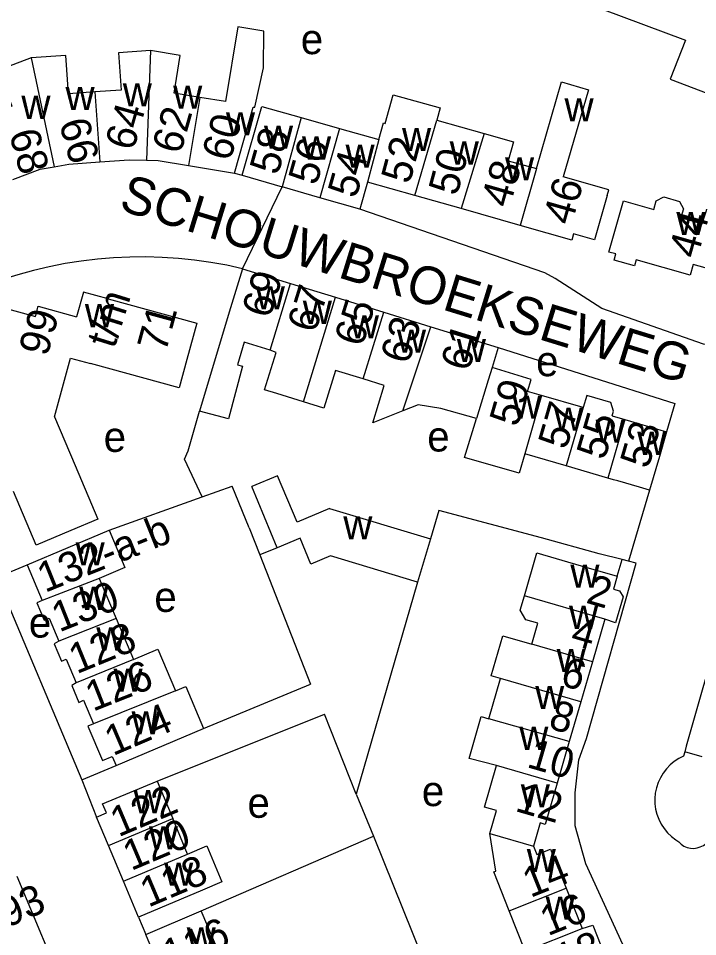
# Model space of a CAD drawing. Extents: x 159261 to 160849, y 382514 to 384534.
# Drawn here: x 159917.5 to 160007.7, y 383430.4 to 383552.3 of the extents above; entities that cross this region are included whole.
import ezdxf

# ---------------------------------------------------------------- set-up
doc = ezdxf.new("R2010")
doc.units = 0
for name, color, linetype in [('BLT_Basislijn', 7, 'Continuous'), ('BLT_Bebouwing', 7, 'Continuous'), ('BLT_Centroide', 7, 'Continuous'), ('BLT_Huisnummer', 7, 'Continuous'), ('BLT_Huisnummer_ tussenligend', 7, 'Continuous'), ('BLT_Huisnummer_reeks', 7, 'Continuous'), ('BLT_Onderverdeling_panden', 7, 'Continuous'), ('BLT_Straatnaam', 7, 'Continuous'), ('BLT_Vlakafsluiter', 7, 'Continuous')]:
    doc.layers.add(name, color=color, linetype=linetype)

msp = doc.modelspace()

# ---------------------------------------------------------------- linework, layer by layer
at = {"layer": 'BLT_Basislijn'}
for p, q in [((159941.95, 383488.76), (159945.92, 383490.19)), ((159948.18, 383484.66), (159945.92, 383490.19)), ((159929.56, 383484.35), (159941.95, 383488.76)), ((160001.36, 383489.65), (159998.56, 383480.21)), ((159951.91, 383482.01), (159949.6, 383481.04)), ((159997.06, 383478.21), (159997.72, 383480.42)), ((159914.62, 383478.06), (159918.68, 383479.74)), ((159914.62, 383478.06), (159925.95, 383451.2)), ((159970.55, 383477.43), (159962.4, 383449.28)), ((159942.13, 383457.98), (159956.32, 383463.89)), ((159935.97, 383451.01), (159958.18, 383459.92)), ((159962.4, 383449.28), (159958.18, 383459.92)), ((160008.35, 383454.22), (160006.03, 383454.89)), ((159925.95, 383451.2), (159930.51, 383453.07)), ((159925.95, 383451.2), (159927.91, 383446.24)), ((159962.4, 383449.28), (159964.68, 383443.7)), ((159941.82, 383433.77), (159964.68, 383443.7)), ((159964.68, 383443.7), (159978.73, 383408.97)), ((159926.45, 383416.69), (159917.36, 383438.35)), ((159933.48, 383432.95), (159934.45, 383430.65))]:
    msp.add_line(p, q, dxfattribs=at)
for points in [[(159935.34, 383566.83), (159950.74, 383571.9), (159950.72, 383570.15), (160006.11, 383549.4), (160004.08, 383544.22), (160019.68, 383538.31)], [(159946.23, 383531.75), (159947.26, 383531.47)], [(160016.26, 383531.1), (160010.01, 383508.78), (160008.53, 383509.02), (159995, 383513.79), (159988.8, 383517.76), (159987.45, 383518.5), (159962.86, 383526.95)], [(159947.3, 383519.06), (159945.19, 383519.52), (159943.07, 383519.9), (159940.93, 383520.2), (159938.79, 383520.42), (159936.63, 383520.56), (159934.47, 383520.62), (159932.32, 383520.61), (159930.16, 383520.51), (159928.01, 383520.33), (159925.87, 383520.07), (159923.73, 383519.74), (159921.62, 383519.32), (159919.52, 383518.83), (159917.43, 383518.26), (159915.38, 383517.61), (159913.34, 383516.89), (159911.34, 383516.09), (159909.36, 383515.22), (159907.42, 383514.27), (159905.52, 383513.26), (159903.65, 383512.17), (159901.83, 383511.02), (159900.97, 383510.44)], [(159981.27, 383508.6), (160004.73, 383501.16), (160003.61, 383497.41)], [(159941.95, 383488.76), (159939.57, 383493.78), (159940.06, 383494.87), (159941.59, 383500.13)], [(159973.38, 383486.97), (159972.28, 383483.18)], [(159997.72, 383480.42), (159994.68, 383481.19), (159987.01, 383483.34), (159973.38, 383486.97)], [(159948.18, 383484.66), (159949.6, 383481.04)], [(159949.6, 383481.04), (159956.32, 383463.89)], [(160008.79, 383416.3), (160007.65, 383418.48), (160006.78, 383418.91), (160000.03, 383424.5), (159992.9, 383440.01), (159991.46, 383445.07), (159991.46, 383449.46), (159991.95, 383453.84), (159992.99, 383456.67), (159999.56, 383479.96), (159998.56, 383480.21)], [(159998.56, 383480.21), (159997.72, 383480.42)], [(160011.91, 383475.28), (160008.45, 383463.41), (160006.23, 383455.63), (160006.03, 383454.89)], [(160006.03, 383454.89), (160005.87, 383454.33)], [(160005.87, 383454.33), (160005.24, 383454.01), (160004.64, 383453.62), (160004.09, 383453.16), (160003.59, 383452.64), (160003.16, 383452.08), (160002.79, 383451.46), (160002.49, 383450.81), (160002.27, 383450.13), (160002.12, 383449.43), (160002.06, 383448.72), (160002.07, 383448.01), (160002.16, 383447.3), (160002.34, 383446.61), (160002.58, 383445.94), (160002.9, 383445.3), (160003.3, 383444.7), (160003.75, 383444.15), (160004.26, 383443.65), (160004.83, 383443.21), (160005.24, 383442.96)], [(160005.24, 383442.96), (160005.56, 383442.64), (160005.93, 383442.39), (160006.34, 383442.21), (160006.78, 383442.11), (160007.23, 383442.08), (160007.67, 383442.13), (160008.1, 383442.26), (160008.5, 383442.47), (160008.86, 383442.74), (160009.16, 383443.07), (160009.4, 383443.45), (160009.6, 383443.95)]]:
    msp.add_lwpolyline(points, dxfattribs=at)
at = {"layer": 'BLT_Bebouwing'}
for p, q in [((159955.1, 383539.13), (159960.16, 383537.69)), ((159940.11, 383532.77), (159946.23, 383531.75)), ((159963.89, 383530.56), (159962.86, 383526.95)), ((159970.2, 383528.77), (159963.89, 383530.56)), ((159957.55, 383528.49), (159952.54, 383529.94)), ((159962.86, 383526.95), (159957.55, 383528.49)), ((159976.32, 383527.04), (159970.2, 383528.77)), ((159995.71, 383528.78), (159994.05, 383522.91)), ((159984.17, 383524.81), (159976.32, 383527.04)), ((159987.74, 383523.8), (159984.17, 383524.81)), ((159991.04, 383522.86), (159987.74, 383523.8)), ((159991.27, 383523.69), (159991.04, 383522.86)), ((159994.05, 383522.91), (159991.27, 383523.69)), ((159947.3, 383519.06), (159953.68, 383517.09)), ((159953.68, 383517.09), (159959.64, 383515.26)), ((159959.64, 383515.26), (159966.04, 383513.29)), ((159966.04, 383513.29), (159972.29, 383511.36)), ((159972.29, 383511.36), (159981.27, 383508.6)), ((159981.27, 383508.6), (159980.45, 383505.94)), ((159922.33, 383499.38), (159924.46, 383507.19)), ((159924.46, 383507.19), (159927.12, 383506.47)), ((159992.53, 383500.62), (159987.02, 383502.22)), ((159922.33, 383499.38), (159925.06, 383492.91)), ((159996.38, 383499.51), (159998.07, 383499.02)), ((159998.07, 383499.02), (160000, 383498.46)), ((160000, 383498.46), (160003.61, 383497.41)), ((160003.61, 383497.41), (160002.66, 383494.11)), ((159990.29, 383492.86), (159984.77, 383494.46)), ((160002.66, 383494.11), (160001.36, 383489.65)), ((159995.82, 383491.25), (159990.29, 383492.86)), ((159951.91, 383482.01), (159948.54, 383490.12)), ((160001.36, 383489.65), (160000, 383490.04)), ((159918.68, 383479.74), (159929.56, 383484.35)), ((159918.68, 383479.74), (159920.67, 383474.98)), ((159928.27, 383477.92), (159930.52, 383472.61)), ((159930.52, 383472.61), (159932.82, 383467.17)), ((159995.41, 383472.5), (159993.77, 383466.86)), ((159993.77, 383466.86), (159992.23, 383461.55)), ((159992.23, 383461.55), (159990.69, 383456.27)), ((159930.51, 383453.07), (159942.13, 383457.98)), ((159990.69, 383456.27), (159989.09, 383450.75)), ((159935.97, 383451.01), (159938.02, 383446.06)), ((159929.49, 383442.46), (159927.91, 383446.24)), ((159939.98, 383441.31), (159938.02, 383446.06)), ((159931.48, 383437.72), (159929.49, 383442.46)), ((159933.48, 383432.95), (159931.48, 383437.72)), ((159990.28, 383436.77), (159992.39, 383431.42)), ((159944.95, 383426.37), (159941.82, 383433.77)), ((159984.83, 383428.44), (159982.72, 383433.78)), ((159937.58, 383423.24), (159934.45, 383430.65))]:
    msp.add_line(p, q, dxfattribs=at)
for points in [[(159948.95, 383540.5), (159950.1, 383545.73), (159950.13, 383550.61), (159946.66, 383551.18), (159945.01, 383541.25), (159941.61, 383541.81)], [(159927.68, 383542.54), (159924.18, 383542.3), (159923.83, 383547.37), (159919.23, 383547.05)], [(159935.09, 383548.05), (159930.83, 383547.75), (159931.18, 383542.78), (159927.68, 383542.54)], [(159941.61, 383541.81), (159938.21, 383542.38), (159939.02, 383547.36), (159935.09, 383548.05)], [(159919.23, 383547.05), (159914.87, 383545.43), (159916.65, 383540.64), (159913.57, 383539.5)], [(159986.35, 383532.37), (159989.67, 383543.87), (159993.25, 383542.82), (159989.88, 383531.27)], [(159965.4, 383536.21), (159966.02, 383538.42), (159966.23, 383538.36), (159967.31, 383542.17), (159973.55, 383540.41), (159973.1, 383538.8)], [(159946.23, 383531.75), (159948.71, 383540.53), (159948.95, 383540.5)], [(159947.26, 383531.47), (159949.85, 383540.62), (159955.1, 383539.13)], [(159973.1, 383538.8), (159979.41, 383537.01)], [(159960.16, 383537.69), (159965.4, 383536.21)], [(159979.41, 383537.01), (159983.29, 383535.91), (159982.57, 383533.4), (159986.35, 383532.37)], [(159922.28, 383532.6), (159924.21, 383532.96), (159928.32, 383533.25)], [(159928.32, 383533.25), (159932.22, 383533.52), (159934.53, 383533.47)], [(159934.53, 383533.47), (159936.07, 383533.44), (159940.11, 383532.77)], [(159916.77, 383530.9), (159920.41, 383532.26), (159922.28, 383532.6)], [(159947.26, 383531.47), (159952.54, 383529.94)], [(159995.71, 383528.78), (159995.96, 383529.55), (159989.88, 383531.27)], [(159947.3, 383519.06), (159945.52, 383513.28), (159941.59, 383500.13)], [(159929.46, 383515.05), (159926.15, 383515.94), (159925.26, 383512.68)], [(159929.46, 383515.05), (159941.21, 383511.84), (159939.89, 383507.02), (159938.87, 383503.26), (159927.12, 383506.47)], [(159912.03, 383502.09), (159911.52, 383502.23), (159914.76, 383514.09), (159919.78, 383512.72), (159920.15, 383514.08), (159925.26, 383512.68)], [(159950.95, 383508.23), (159947.53, 383509.29), (159946.62, 383506.31), (159947.3, 383506.13), (159945.41, 383499.12), (159941.59, 383500.13)], [(159955.38, 383501.4), (159951.87, 383502.48), (159950.23, 383502.98), (159951.76, 383507.93), (159950.95, 383508.23)], [(159987.02, 383502.22), (159985.14, 383502.77), (159985.62, 383504.35), (159980.45, 383505.94)], [(159963.3, 383504.42), (159959.64, 383505.55), (159958.11, 383500.56), (159955.38, 383501.4)], [(159968.58, 383500.18), (159964.59, 383498.59), (159966.12, 383503.55), (159963.3, 383504.42)], [(159996.38, 383499.51), (159996.56, 383500.14), (159996.23, 383501.29), (159993.01, 383502.24), (159992.53, 383500.62)], [(159978.36, 383499.15), (159973.64, 383500.5), (159970.63, 383501), (159968.58, 383500.18)], [(159984.77, 383494.46), (159984.03, 383491.9), (159976.77, 383493.98), (159978.36, 383499.15)], [(159925.06, 383492.91), (159928.06, 383485.78), (159924.49, 383484.28), (159919.88, 383482.34), (159916.88, 383489.46)], [(159958.85, 383487.22), (159954.56, 383485.4), (159951.95, 383491.57), (159948.54, 383490.12)], [(160000, 383490.04), (159997.14, 383490.87), (159996.56, 383491.04), (159995.82, 383491.25)], [(159958.85, 383487.22), (159972.28, 383483.18)], [(159929.56, 383484.35), (159931.67, 383479.36), (159928.27, 383477.92)], [(159970.55, 383477.43), (159959, 383480.91), (159956.38, 383479.82), (159954.94, 383483.27), (159951.91, 383482.01)], [(159972.28, 383483.18), (159970.55, 383477.43)], [(159984.73, 383475.6), (159986.39, 383481.31), (159992.26, 383479.6), (159997.06, 383478.21)], [(159997.06, 383478.21), (159996.57, 383476.51), (159997.38, 383476.28), (159997.84, 383475.47), (159996.84, 383472.04), (159995.41, 383472.5)], [(159985.71, 383469.2), (159986.52, 383471.98), (159984.93, 383472.45), (159984.17, 383473.7), (159984.73, 383475.6)], [(159920.67, 383474.98), (159919.98, 383474.69), (159920.96, 383472.38), (159921.6, 383472.66), (159922.9, 383469.59)], [(159922.9, 383469.59), (159922.29, 383469.23), (159923.25, 383466.95), (159923.88, 383467.22), (159925.21, 383464.06)], [(159980.33, 383465.01), (159981.87, 383470.32), (159985.71, 383469.2)], [(159932.82, 383467.17), (159936.06, 383468.54), (159938.4, 383463)], [(159980, 383459.3), (159981.55, 383464.65)], [(159981.55, 383464.65), (159980.33, 383465.01)], [(159925.21, 383464.06), (159924.61, 383463.71), (159925.56, 383461.47), (159926.17, 383461.74), (159927.5, 383458.6)], [(159938.4, 383463), (159939.77, 383463.58), (159942.13, 383457.98)], [(159981.03, 383453.09), (159977.38, 383454.03), (159979, 383459.6), (159980, 383459.3)], [(159927.5, 383458.6), (159926.76, 383458.29), (159928.69, 383453.73), (159929.99, 383454.27), (159930.51, 383453.07)], [(159981.01, 383447.11), (159979.43, 383447.57), (159981.03, 383453.09)], [(159927.91, 383446.24), (159929.23, 383446.78), (159928.71, 383447.99), (159935.97, 383451.01)], [(159989.09, 383450.75), (159987.49, 383445.26), (159986.84, 383445.45)], [(159980.12, 383444.06), (159981.01, 383447.11)], [(159986.84, 383445.45), (159985.95, 383442.37)], [(159980.96, 383439.06), (159980.12, 383444.06)], [(159939.98, 383441.31), (159942.54, 383442.4), (159944.55, 383437.63), (159941.96, 383436.53), (159933.48, 383432.95)], [(159985.95, 383442.37), (159986.39, 383441.27)], [(159986.39, 383441.27), (159988.22, 383441.99), (159990.28, 383436.77)], [(159982.72, 383433.78), (159980.68, 383438.95), (159980.96, 383439.06)], [(159934.45, 383430.65), (159941.82, 383433.77)], [(159992.39, 383431.42), (159993.83, 383431.88), (159994.89, 383429.2), (159994.46, 383427.93), (159993.87, 383427.7), (159994.51, 383426.08)]]:
    msp.add_lwpolyline(points, dxfattribs=at)
msp.add_lwpolyline([(159997.89, 383528.09), (160001.91, 383526.92), (160002.25, 383528.07), (160003.24, 383528.61), (160005.33, 383528), (160005.85, 383527.02), (160005.51, 383525.86), (160008.34, 383525.04), (160009.48, 383528.62), (160014.28, 383527.22), (160011.76, 383518.33), (160007.14, 383519.6), (160006.73, 383518.19), (159999.59, 383520.24), (159999.37, 383519.43), (159996.66, 383520.21), (159996.89, 383521.02), (159995.94, 383521.27)], close=True, dxfattribs=at)
at = {"layer": 'BLT_Onderverdeling_panden'}
for p, q in [((159935.09, 383548.05), (159934.53, 383533.47)), ((159919.23, 383547.05), (159922.28, 383532.6)), ((159927.68, 383542.54), (159928.32, 383533.25)), ((159941.61, 383541.81), (159940.11, 383532.77)), ((159955.1, 383539.13), (159952.54, 383529.94)), ((159970.2, 383528.77), (159973.1, 383538.8)), ((159960.16, 383537.69), (159957.55, 383528.49)), ((159979.41, 383537.01), (159976.32, 383527.04)), ((159965.4, 383536.21), (159963.89, 383530.56)), ((159986.35, 383532.37), (159984.17, 383524.81)), ((159950.95, 383508.23), (159953.68, 383517.09)), ((159955.38, 383501.4), (159959.64, 383515.26)), ((159963.3, 383504.42), (159966.04, 383513.29)), ((159968.58, 383500.18), (159972.29, 383511.36)), ((159980.45, 383505.94), (159979.94, 383504.27)), ((159979.94, 383504.27), (159978.36, 383499.15)), ((159987.02, 383502.22), (159984.77, 383494.46)), ((159992.53, 383500.62), (159990.29, 383492.86)), ((159998.07, 383499.02), (159995.82, 383491.25)), ((159928.27, 383477.92), (159920.67, 383474.98)), ((159995.41, 383472.5), (159984.73, 383475.6)), ((159930.52, 383472.61), (159922.9, 383469.59)), ((159993.77, 383466.86), (159985.71, 383469.2)), ((159932.82, 383467.17), (159925.21, 383464.06)), ((159992.23, 383461.55), (159981.55, 383464.65)), ((159938.4, 383463), (159927.5, 383458.6)), ((159990.69, 383456.27), (159980, 383459.3)), ((159989.09, 383450.75), (159981.03, 383453.09)), ((159929.49, 383442.46), (159938.02, 383446.06)), ((159980.12, 383444.06), (159985.95, 383442.37)), ((159931.48, 383437.72), (159939.98, 383441.31)), ((159982.72, 383433.78), (159990.28, 383436.77)), ((159984.83, 383428.44), (159992.39, 383431.42))]:
    msp.add_line(p, q, dxfattribs=at)
at = {"layer": 'BLT_Vlakafsluiter'}
msp.add_line((159947.3, 383519.06), (159952.54, 383529.94), dxfattribs=at)

# ---------------------------------------------------------------- texts
at = {"layer": 'BLT_Centroide'}
for s, p in [('e', (159955.03, 383547.55)), ('w', (159931.39, 383540.62)), ('w', (159923.78, 383540.12)), ('w', (159938.08, 383540.3)), ('w', (159917.92, 383538.95)), ('w', (159990.06, 383538.61)), ('w', (159945.09, 383536.77)), ('w', (159950.14, 383534.98)), ('w', (159968.48, 383534.67)), ('w', (159955.19, 383533.55)), ('w', (159960.97, 383532.47)), ('w', (159974.81, 383532.89)), ('w', (159982.16, 383530.8)), ('w', (160004.91, 383523.53)), ('w', (159949.06, 383513.66)), ('w', (159926.36, 383511.28)), ('w', (159955.3, 383511.73)), ('w', (159961.55, 383509.81)), ('w', (159967.8, 383507.89)), ('w', (159975.76, 383506.66)), ('e', (159986.29, 383504.78)), ('w', (159983.14, 383499.14)), ('w', (159988.66, 383497.55)), ('w', (159994.19, 383495.94)), ('e', (159928.85, 383494.73)), ('e', (159971.83, 383494.78)), ('w', (159999.72, 383494.33)), ('w', (159960.68, 383483.11)), ('w', (159925.12, 383479.66)), ('w', (159990.84, 383476.69)), ('w', (159925.6, 383473.75)), ('e', (159935.58, 383473.48)), ('w', (159990.66, 383471.22)), ('e', (159918.91, 383470.07)), ('w', (159927.88, 383468.34)), ('w', (159989.01, 383465.5)), ('w', (159930.16, 383462.88)), ('w', (159986.16, 383460.59)), ('w', (159932.55, 383457.22)), ('w', (159984.05, 383455.16)), ('w', (159932.82, 383446.75)), ('e', (159971.11, 383447.69)), ('w', (159984.25, 383447.52)), ('e', (159947.95, 383446.14)), ('w', (159934.85, 383441.94)), ('w', (159985.05, 383438.94)), ('w', (159936.88, 383437.12)), ('w', (159987.55, 383432.59)), ('w', (159939.88, 383428.53))]:
    msp.add_text(s, height=4, dxfattribs=at).set_placement(p)
at = {"layer": 'BLT_Huisnummer'}
for s, rotation, p in [('62', 74.1717, (159939.05, 383534.13)), ('66', 285.6019, (159922.89, 383538.45)), ('58', 74.1709, (159951.99, 383531.35)), ('52', 75.0325, (159969.48, 383530.17)), ('54', 74.1698, (159962.37, 383528.28)), ('46', 74.1719, (159990.98, 383524.7)), ('44', 74.1719, (160007.67, 383520.26)), ('69', 72.8705, (159950.92, 383512.32)), ('65', 72.8659, (159963.21, 383508.55)), ('61', 72.8945, (159977.33, 383505.27)), ('59', 73.8385, (159983.84, 383497.92)), ('53', 73.8385, (160001.19, 383492.37)), ('2', 343.7985, (159992.77, 383474.73)), ('128', 22.2058, (159925.26, 383465.19)), ('6', 343.7985, (159989.33, 383463.79)), ('124', 23.1911, (159930.08, 383454.31)), ('10', 343.7985, (159984.91, 383452.9)), ('122', 22.9442, (159930.81, 383443.53)), ('14', 21.7948, (159985.52, 383435.48)), ('116', 22.9316, (159937.72, 383425.89)), ('18', 21.7975, (159989.86, 383425.34))]:
    msp.add_text(s, height=4, rotation=rotation, dxfattribs=at).set_placement(p)
at = {"layer": 'BLT_Huisnummer_ tussenligend'}
for s, rotation, p in [('64', 74.1717, (159932.8, 383534.58)), ('60', 74.1709, (159945.66, 383533.19)), ('68', 285.6019, (159916.25, 383537.03)), ('56', 74.1698, (159957.13, 383529.99)), ('50', 75.0325, (159975.78, 383528.61)), ('48', 74.1719, (159982.75, 383527.01)), ('67', 72.8659, (159956.96, 383510.39)), ('63', 72.8945, (159969.33, 383506.23)), ('57', 73.8385, (159990.3, 383494.91)), ('55', 73.8385, (159995.4, 383493.53)), ('130', 21.643, (159922.95, 383470.74)), ('4', 343.7985, (159990.68, 383469.18)), ('126', 21.5979, (159927.43, 383460.21)), ('8', 343.7985, (159987.77, 383458.07)), ('12', 343.7985, (159983.36, 383447.07)), ('120', 22.9316, (159932.49, 383439.05)), ('118', 22.9316, (159934.78, 383434.19)), ('16', 21.7948, (159987.84, 383430.39))]:
    msp.add_text(s, height=4, rotation=rotation, dxfattribs=at).set_placement(p)
at = {"layer": 'BLT_Huisnummer_reeks'}
for s, rotation, p in [('t/m', 72.6501, (159930.28, 383508.33)), ('99', 74.0874, (159921.34, 383507.27)), ('71', 74.7423, (159937.09, 383507.83)), ('132-a-b', 21.9357, (159921.05, 383475.99)), ('91-93', 23.209, (159908.87, 383428.43))]:
    msp.add_text(s, height=4, rotation=rotation, dxfattribs=at).set_placement(p)
at = {"layer": 'BLT_Straatnaam'}
msp.add_text('SCHOUWBROEKSEWEG', height=4.9999, rotation=342.8839, dxfattribs=at).set_placement((159930.71, 383526.92))

doc.saveas('drawing.dxf')
